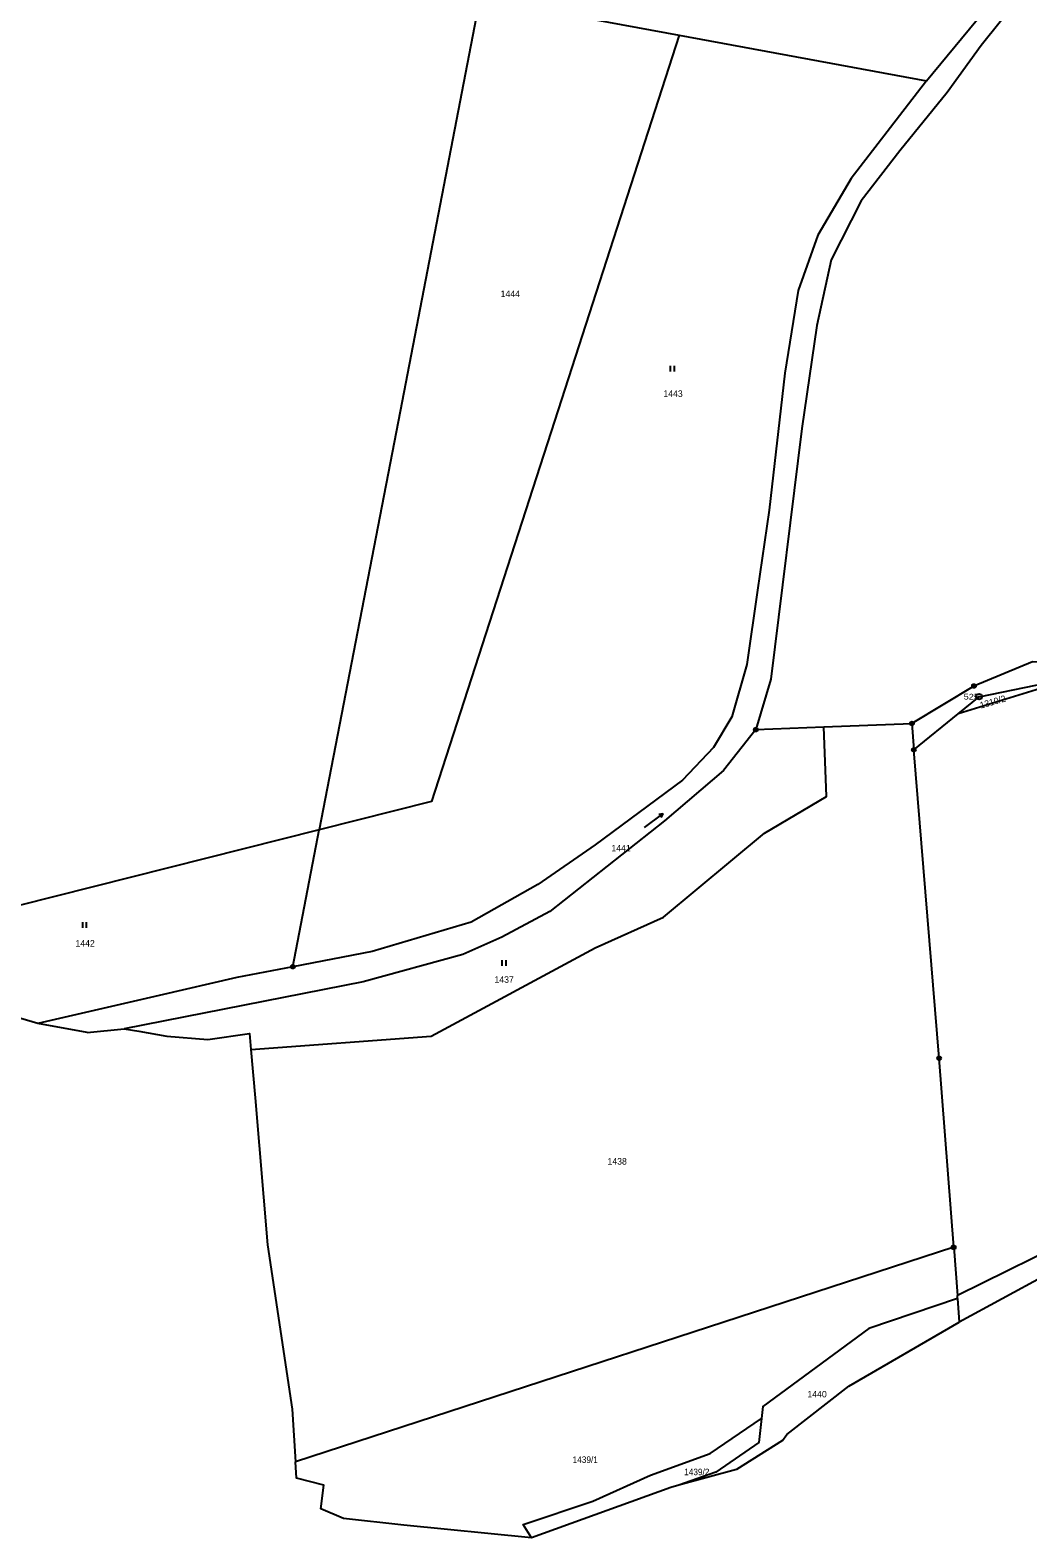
# Model space of a CAD drawing. Extents: x -872229 to -869198, y -1075981 to -1074329.
# Drawn here: x -870893.1 to -870632.3, y -1075980.9 to -1075586.7 of the extents above; entities that cross this region are included whole.
import ezdxf
from ezdxf.enums import TextEntityAlignment as Align

# ---------------------------------------------------------------- set-up
doc = ezdxf.new("R2010")
doc.units = 0
doc.header["$LTSCALE"] = 0.68
for name, color, linetype, lineweight in [('1', 7, 'Continuous', 25), ('3', 7, 'Continuous', 25), ('8', 7, 'Continuous', 25)]:
    doc.layers.add(name, color=color, linetype=linetype, lineweight=lineweight)
doc.layers.add('2', color=7, linetype='Continuous')

msp = doc.modelspace()

# ---------------------------------------------------------------- linework, layer by layer
at = {"layer": '1'}
for p, q in [((-870618.4, -1075755.49), (-870650.51, -1075765.39)), ((-870878.19, -1075848.76), (-870891.16, -1075846.37)), ((-870878.19, -1075848.76), (-870868.54, -1075847.76)), ((-870835.43, -1075853.18), (-870834.35, -1075865.8)), ((-870651.69, -1075904.9), (-870823.75, -1075960.94)), ((-870651.69, -1075904.9), (-870650.72, -1075917.52)), ((-870650.66, -1075918.25), (-870650.72, -1075917.52)), ((-870650.66, -1075918.25), (-870650.23, -1075924.48)), ((-870713.83, -1075963.64), (-870723.53, -1075967.1)), ((-870795.41, -1075977.55), (-870811.25, -1075975.79))]:
    msp.add_line(p, q, dxfattribs=at)
for points in [[(-870769.48, -1075546.88), (-870775.56, -1075578.36), (-870723.44, -1075587.98), (-870658.76, -1075599.92), (-870633.02, -1075568.68)], [(-870775.56, -1075578.36), (-870796.43, -1075686.4), (-870817.54, -1075795.72)], [(-870634.57, -1075578.24), (-870644.53, -1075590.75), (-870653.4, -1075603.02), (-870665.74, -1075618.29), (-870675.84, -1075631.34), (-870683.76, -1075646.76), (-870687.46, -1075663.9), (-870691.39, -1075690.84), (-870699.49, -1075756.36), (-870703.4, -1075769.57), (-870685.61, -1075768.87), (-870662.6, -1075767.96)], [(-870723.44, -1075587.98), (-870756.06, -1075688.89), (-870788.21, -1075788.31), (-870817.54, -1075795.72)], [(-870497.88, -1075584.92), (-870501.24, -1075597.99), (-870508.17, -1075703.33), (-870541.87, -1075736.74), (-870558.64, -1075743.46), (-870618.91, -1075752.53), (-870631.08, -1075751.8), (-870646.39, -1075758.16), (-870662.6, -1075767.96)], [(-870658.76, -1075599.92), (-870678.46, -1075625.49), (-870687.24, -1075640.3), (-870692.36, -1075654.75), (-870695.8, -1075676.34), (-870699.97, -1075712.19), (-870702.99, -1075733.08), (-870705.81, -1075752.56), (-870709.71, -1075766.23), (-870714.5, -1075774.23), (-870722.58, -1075782.75), (-870745.39, -1075799.68), (-870760.4, -1075810.04), (-870777.81, -1075819.9), (-870803.76, -1075827.6), (-870824.46, -1075831.55), (-870817.54, -1075795.72), (-870984.88, -1075837.95)], [(-870650.51, -1075765.39), (-870645.07, -1075760.95), (-870618.4, -1075755.49), (-870560.25, -1075746.77), (-870557.85, -1075746.37)], [(-870662.6, -1075767.96), (-870662.1, -1075774.86), (-870650.51, -1075765.39)], [(-870835.43, -1075853.18), (-870788.29, -1075849.73), (-870745.46, -1075826.63), (-870727.54, -1075818.59), (-870701.15, -1075796.59), (-870684.9, -1075787.01), (-870685.61, -1075768.87)], [(-870703.4, -1075769.57), (-870711.89, -1075780.25), (-870727.3, -1075793.42), (-870757.25, -1075817.1), (-870769.85, -1075823.85), (-870780.02, -1075828.35), (-870806.1, -1075835.5), (-870868.54, -1075847.76)], [(-870651.69, -1075904.9), (-870655.48, -1075855.47), (-870662.1, -1075774.86)], [(-870824.46, -1075831.55), (-870839.13, -1075834.34), (-870859.41, -1075839.03), (-870891.16, -1075846.37)], [(-870891.16, -1075846.37), (-870900.85, -1075843.51), (-870915.96, -1075844.76), (-870940.05, -1075843.27), (-870969.07, -1075840.28), (-870984.88, -1075837.95)], [(-870868.54, -1075847.76), (-870864.68, -1075848.42), (-870857.37, -1075849.66), (-870846.7, -1075850.59), (-870835.79, -1075848.98), (-870835.43, -1075853.18)], [(-870549.14, -1075861.93), (-870617.86, -1075901.31), (-870650.72, -1075917.52)], [(-870834.35, -1075865.8), (-870831.07, -1075904.26), (-870824.66, -1075947.17), (-870823.75, -1075960.94)], [(-870546.66, -1075871.21), (-870616.52, -1075906.2), (-870650.23, -1075924.48)], [(-870650.66, -1075918.25), (-870673.9, -1075926.14), (-870701.61, -1075946.51), (-870701.96, -1075949.68)], [(-870696.44, -1075955.38), (-870695.33, -1075953.82), (-870679.07, -1075941.16), (-870650.23, -1075924.48)], [(-870762.08, -1075980.85), (-870764.28, -1075977.33), (-870746.06, -1075971.25), (-870730.99, -1075964.47), (-870715.35, -1075958.8), (-870701.96, -1075949.68)], [(-870701.96, -1075949.68), (-870702.66, -1075955.95), (-870713.83, -1075963.64)], [(-870696.44, -1075955.38), (-870708.5, -1075963), (-870723.53, -1075967.1)], [(-870811.25, -1075975.79), (-870817.18, -1075973.25), (-870816.39, -1075967.05), (-870823.46, -1075965.24), (-870823.75, -1075960.94)], [(-870723.53, -1075967.1), (-870725.66, -1075967.68), (-870762.08, -1075980.85), (-870795.41, -1075977.55)]]:
    msp.add_lwpolyline(points, dxfattribs=at)
at = {"layer": '3'}
for p, q in [((-870725.691, -1075675.97), (-870725.691, -1075674.47)), ((-870724.69, -1075675.97), (-870724.69, -1075674.47)), ((-870727.735, -1075791.571), (-870728.214, -1075792.56)), ((-870879.401, -1075821.41), (-870879.401, -1075819.91)), ((-870878.4, -1075821.41), (-870878.4, -1075819.91)), ((-870769.711, -1075831.33), (-870769.711, -1075829.83)), ((-870768.71, -1075831.33), (-870768.71, -1075829.83))]:
    msp.add_line(p, q, dxfattribs=at)
msp.add_lwpolyline([(-870732.527, -1075795.182), (-870727.735, -1075791.571), (-870728.817, -1075791.759)], dxfattribs=at)
at = {"layer": '8'}
for centre, radius in [((-870646.39, -1075758.1599), 0.5), ((-870646.39, -1075758.1599), 0.0303), ((-870645.07, -1075760.9498), 0.75), ((-870645.07, -1075760.9498), 0.03), ((-870703.4, -1075769.5699), 0.5), ((-870662.6, -1075767.9599), 0.5), ((-870662.6, -1075767.9599), 0.0303), ((-870703.4, -1075769.5699), 0.0303), ((-870662.1, -1075774.8599), 0.5), ((-870662.1, -1075774.8599), 0.0303), ((-870824.46, -1075831.5499), 0.5), ((-870824.46, -1075831.5499), 0.0303), ((-870655.48, -1075855.4699), 0.5), ((-870655.48, -1075855.4699), 0.0303), ((-870651.69, -1075904.8999), 0.5), ((-870651.69, -1075904.8999), 0.0303)]:
    msp.add_circle(centre, radius, dxfattribs=at)

# ---------------------------------------------------------------- texts
at = {"layer": '2'}
for s, p in [('1444', (-870770.13, -1075656.47)), ('1443', (-870727.59, -1075682.58)), ('1441', (-870741.17, -1075801.4)), ('1442', (-870881.29, -1075826.29)), ('1437', (-870771.75, -1075835.75)), ('1438', (-870742.2, -1075883.27)), ('1440', (-870689.93, -1075944.14))]:
    msp.add_text(s, height=1.7, dxfattribs=at).set_placement(p)
msp.add_text('1310/2', height=1.7, rotation=16, dxfattribs=at).set_placement((-870644.575, -1075764.067))
at = {"layer": '2', "width": 0.95}
for s, p in [('1439/1', (-870748.009, -1075961.26)), ('1439/2', (-870718.849, -1075964.47))]:
    msp.add_text(s, height=1.7, dxfattribs=at).set_placement(p, align=Align.CENTER)
at = {"layer": '8', "width": 1.2}
msp.add_text('525', height=1.5, dxfattribs=at).set_placement((-870645.07, -1075761.7), align=Align.RIGHT)

doc.saveas('drawing.dxf')
